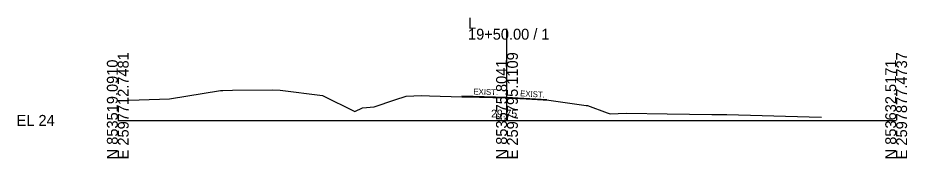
# Model space of a CAD drawing. Extents: x -26 to 1203, y -10 to 9526.
# Drawn here: x -25.7 to 202.8, y 9490.3 to 9526.3 of the extents above; entities that cross this region are included whole.
import ezdxf

# ---------------------------------------------------------------- set-up
doc = ezdxf.new("R2010")
doc.units = 0
for name, color, linetype in [('Exist Cross Section Cell', 7, 'Continuous'), ('Exist XS Center Line Elevation Label', 7, 'Continuous'), ('Exist XS Ground Line', 7, 'Continuous'), ('Prop XS Finish Grade Pavement', 7, 'Continuous'), ('Prop XS SE Text', 7, 'Continuous')]:
    doc.layers.add(name, color=color, linetype=linetype)

msp = doc.modelspace()

# ---------------------------------------------------------------- linework, layer by layer
at = {"layer": 'Exist Cross Section Cell'}
for p, q in [((100, 9500), (100, 9523.51)), ((0, 9500), (100, 9500)), ((100, 9500), (200, 9500))]:
    msp.add_line(p, q, dxfattribs=at)
at = {"layer": 'Exist XS Ground Line'}
for p, q in [((13.26, 9505.49), (26.43, 9507.64)), ((26.43, 9507.64), (27.01, 9507.7)), ((27.01, 9507.7), (29.49, 9507.73)), ((29.49, 9507.73), (39.69, 9507.84)), ((39.69, 9507.84), (41.72, 9507.78)), ((41.72, 9507.78), (52.62, 9506.38)), ((0, 9505.12), (0.29, 9505.12)), ((0.29, 9505.12), (13.26, 9505.49)), ((52.62, 9506.38), (60.88, 9502.25)), ((65.88, 9503.5), (71.2, 9505.27)), ((71.2, 9505.27), (74.07, 9506.23)), ((74.07, 9506.23), (78.07, 9506.36)), ((78.07, 9506.36), (80.07, 9506.3)), ((80.07, 9506.3), (88.37, 9506.06)), ((88.37, 9506.06), (89.64, 9506.02)), ((89.64, 9506.02), (99.67, 9505.77)), ((99.67, 9505.77), (100, 9505.75)), ((100, 9505.75), (104.89, 9505.49)), ((104.89, 9505.49), (110.73, 9505.18)), ((110.73, 9505.18), (120.33, 9503.82)), ((60.88, 9502.25), (62.88, 9503.25)), ((62.88, 9503.25), (65.88, 9503.5)), ((120.33, 9503.82), (120.65, 9503.78)), ((120.65, 9503.78), (125.72, 9501.95)), ((125.72, 9501.95), (126.54, 9501.67)), ((126.54, 9501.67), (128.59, 9501.76)), ((128.59, 9501.76), (130.81, 9501.82)), ((130.81, 9501.82), (141.2, 9501.71)), ((141.2, 9501.71), (152.66, 9501.53)), ((152.66, 9501.53), (156.49, 9501.5)), ((156.49, 9501.5), (177.69, 9500.95)), ((177.69, 9500.95), (180.78, 9500.85))]:
    msp.add_line(p, q, dxfattribs=at)
at = {"layer": 'Prop XS Finish Grade Pavement'}
for p, q in [((88.38, 9506.28), (100, 9505.94)), ((100, 9505.94), (110.25, 9505.32))]:
    msp.add_line(p, q, dxfattribs=at)

# ---------------------------------------------------------------- texts
at = {"layer": 'Exist Cross Section Cell'}
for s, p in [('L', (90, 9523.51)), ('19+50.00 / 1', (90, 9520.71)), ('EL 24', (-26, 9498.6))]:
    msp.add_text(s, height=2.8, dxfattribs=at).set_placement(p)
for s, p in [('E 2597712.7481', (2.8, 9490)), ('E 2597795.1109', (102.8, 9490)), ('E 2597877.4737', (202.8, 9490)), ('N 853519.0910', (0, 9490)), ('N 853575.8041', (100, 9490)), ('N 853632.5171', (200, 9490))]:
    msp.add_text(s, height=2.8, rotation=90, dxfattribs=at).set_placement(p)
at = {"layer": 'Exist XS Center Line Elevation Label'}
msp.add_text('29.75', height=2, dxfattribs=at).set_placement((95.93, 9500.75))
at = {"layer": 'Prop XS SE Text'}
for rotation, p in [(358.2816, (91.35, 9506.66)), (356.5664, (103.35, 9506.2))]:
    msp.add_text('EXIST.', height=1.5, rotation=rotation, dxfattribs=at).set_placement(p)

doc.saveas('drawing.dxf')
